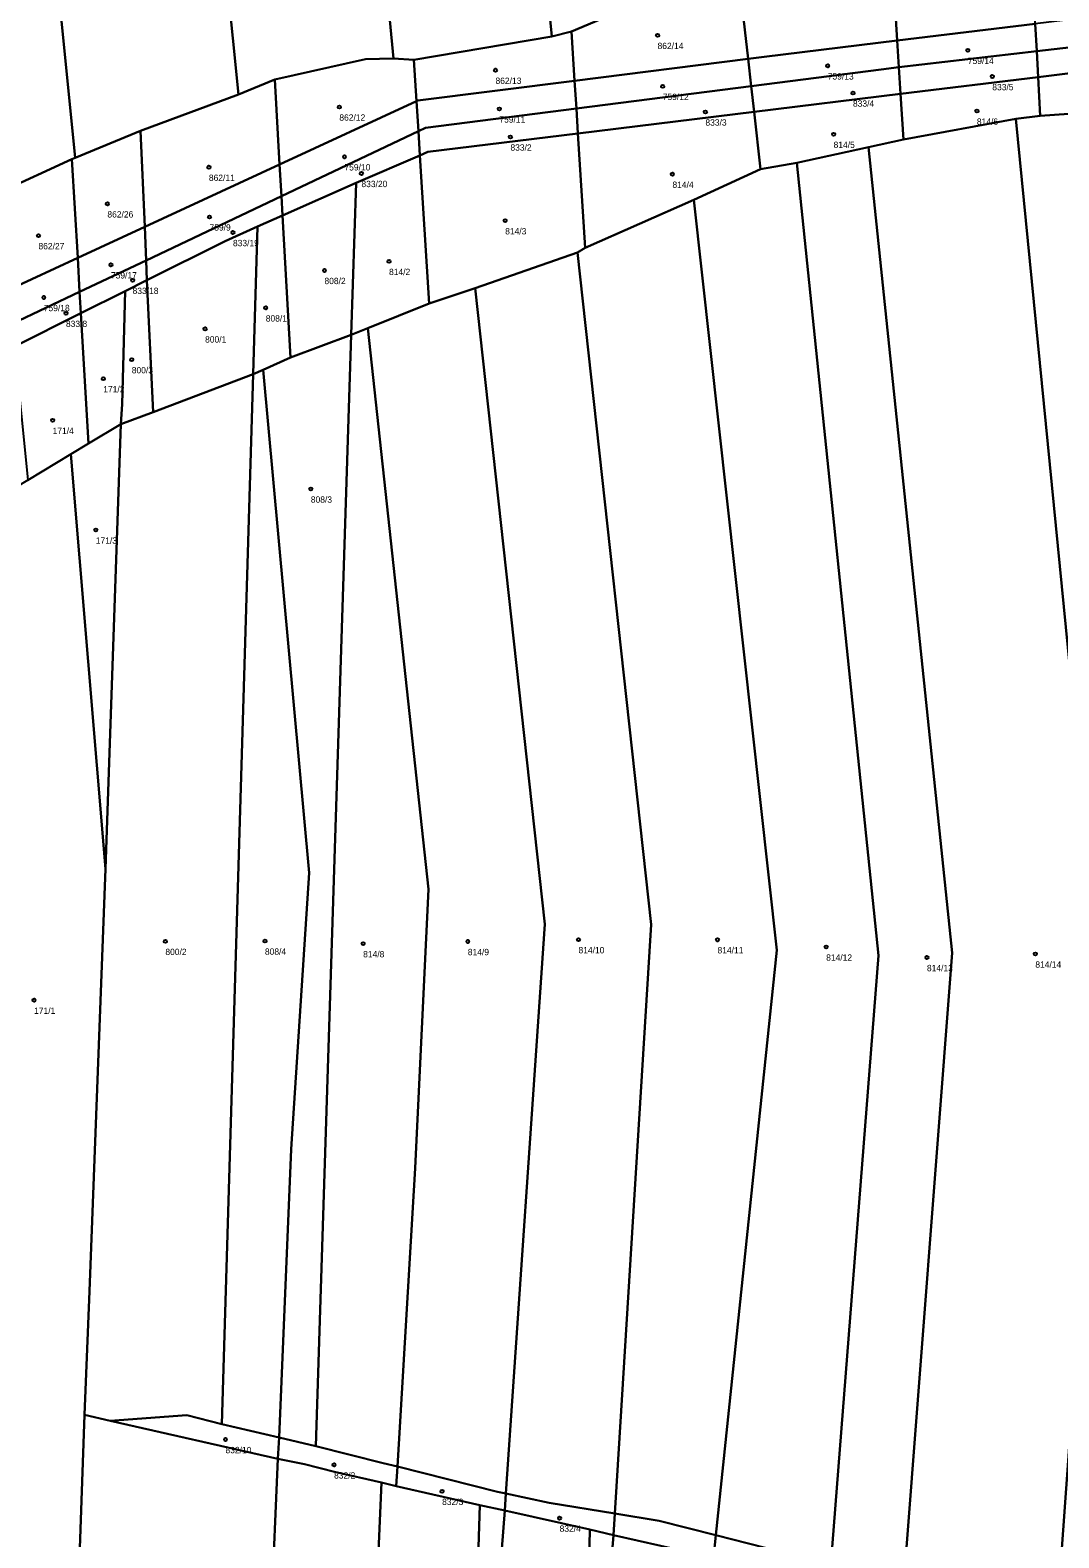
# Model space of a CAD drawing. Extents: x -587171 to -555306, y -1167727 to -1074732.
# Drawn here: x -585632 to -585469.6, y -1165047.9 to -1164809.8 of the extents above; entities that cross this region are included whole.
import ezdxf

# ---------------------------------------------------------------- set-up
doc = ezdxf.new("R2010")
doc.units = 0
doc.layers.add('Definiční body', color=7, linetype='Continuous')
doc.layers.add('Polygon parcely', color=7, linetype='Continuous')

msp = doc.modelspace()

# ---------------------------------------------------------------- linework, layer by layer
at = {"layer": 'Definiční body'}
for centre in [(-585532.92, -1164810.65), (-585483.92, -1164813.01), (-585558.51, -1164816.15), (-585506.04, -1164815.46), (-585480.06, -1164817.15), (-585532.1, -1164818.7), (-585583.17, -1164821.96), (-585502.06, -1164819.75), (-585557.9, -1164822.27), (-585525.36, -1164822.74), (-585482.49, -1164822.6), (-585556.15, -1164826.69), (-585505.12, -1164826.27), (-585603.77, -1164831.47), (-585582.36, -1164829.82), (-585579.68, -1164832.45), (-585530.57, -1164832.57), (-585619.8, -1164837.25), (-585603.67, -1164839.32), (-585556.98, -1164839.92), (-585630.68, -1164842.27), (-585599.97, -1164841.78), (-585619.24, -1164846.88), (-585585.52, -1164847.77), (-585575.32, -1164846.34), (-585615.82, -1164849.33), (-585629.84, -1164852.04), (-585626.34, -1164854.54), (-585594.79, -1164853.68), (-585604.37, -1164857), (-585615.95, -1164861.86), (-585620.45, -1164864.87), (-585628.45, -1164871.43), (-585587.67, -1164882.29), (-585621.63, -1164888.77), (-585610.64, -1164953.73), (-585594.92, -1164953.68), (-585579.41, -1164954.09), (-585562.88, -1164953.75), (-585545.4, -1164953.45), (-585523.45, -1164953.47), (-585506.29, -1164954.62), (-585490.38, -1164956.28), (-585473.26, -1164955.72), (-585631.37, -1164963.01), (-585601.15, -1165032.4), (-585584, -1165036.4), (-585566.94, -1165040.58), (-585548.39, -1165044.81)]:
    msp.add_circle(centre, 0.25, dxfattribs=at)
at = {"layer": 'Polygon parcely'}
for points in [[(-585551, -1164580.28), (-585573.84, -1164584.79), (-585561.86, -1164685.88), (-585549.62, -1164810.82), (-585546.52, -1164810.02), (-585526.98, -1164801.79), (-585538.96, -1164683.24)], [(-585573.84, -1164584.79), (-585598.1, -1164589.57), (-585585.8, -1164697.59), (-585574.62, -1164814.28), (-585571.39, -1164814.49), (-585549.62, -1164810.82), (-585561.86, -1164685.88)], [(-585610.53, -1164706.4), (-585599.09, -1164819.98), (-585593.35, -1164817.59), (-585579.04, -1164814.41), (-585574.62, -1164814.28), (-585585.8, -1164697.59), (-585598.1, -1164589.57), (-585611.87, -1164592.28), (-585621.99, -1164594.46)], [(-585647.86, -1164600.03), (-585636.36, -1164715.01), (-585624.87, -1164829.97), (-585614.56, -1164825.73), (-585599.09, -1164819.98), (-585610.53, -1164706.4), (-585621.99, -1164594.46)], [(-585624.87, -1164829.97), (-585636.36, -1164715.01), (-585647.86, -1164600.03), (-585673.24, -1164605.5), (-585661.76, -1164722.49), (-585650.38, -1164838.45), (-585636.88, -1164835.45), (-585625.4, -1164830.19)], [(-585475.09, -1164775.69), (-585476.81, -1164776.66), (-585494.84, -1164785.46), (-585496.61, -1164786.37), (-585495.06, -1164811.47), (-585473.28, -1164808.8)], [(-585495.06, -1164811.47), (-585496.61, -1164786.37), (-585503.91, -1164790.2), (-585520.33, -1164799.18), (-585518.61, -1164814.37), (-585516.08, -1164814.05)], [(-585520.33, -1164799.18), (-585526.98, -1164801.79), (-585546.52, -1164810.02), (-585546.02, -1164817.81), (-585518.61, -1164814.37)], [(-585473.04, -1164813.15), (-585454.28, -1164810.97), (-585454.82, -1164806.58), (-585458.23, -1164806.96), (-585473.28, -1164808.8)], [(-585473.28, -1164808.8), (-585495.06, -1164811.47), (-585494.8, -1164815.68), (-585473.04, -1164813.15)], [(-585546.52, -1164810.02), (-585549.62, -1164810.82), (-585571.39, -1164814.49), (-585570.99, -1164821.02), (-585570.78, -1164820.92), (-585546.02, -1164817.81)], [(-585516.08, -1164814.05), (-585518.61, -1164814.37), (-585518.13, -1164818.65), (-585497.6, -1164816.01), (-585494.8, -1164815.68), (-585495.06, -1164811.47)], [(-585454.28, -1164810.97), (-585473.04, -1164813.15), (-585472.82, -1164817.23), (-585453.8, -1164814.9)], [(-585571.39, -1164814.49), (-585574.62, -1164814.28), (-585579.04, -1164814.41), (-585593.35, -1164817.59), (-585592.6, -1164831.03), (-585570.99, -1164821.02)], [(-585518.61, -1164814.37), (-585546.02, -1164817.81), (-585545.74, -1164822.19), (-585518.13, -1164818.65)], [(-585473.04, -1164813.15), (-585494.8, -1164815.68), (-585494.54, -1164819.9), (-585472.82, -1164817.23)], [(-585494.54, -1164819.9), (-585494.8, -1164815.68), (-585497.6, -1164816.01), (-585518.13, -1164818.65), (-585517.67, -1164822.74)], [(-585453.8, -1164814.9), (-585472.82, -1164817.23), (-585472.49, -1164823.33), (-585452.91, -1164821.98)], [(-585599.09, -1164819.98), (-585614.56, -1164825.73), (-585613.91, -1164840.9), (-585592.6, -1164831.03), (-585593.35, -1164817.59)], [(-585569.55, -1164825.25), (-585545.74, -1164822.19), (-585546.02, -1164817.81), (-585570.78, -1164820.92), (-585570.99, -1164821.02), (-585570.69, -1164825.79)], [(-585518.13, -1164818.65), (-585545.74, -1164822.19), (-585545.49, -1164826.15), (-585517.67, -1164822.74)], [(-585472.82, -1164817.23), (-585494.54, -1164819.9), (-585494.1, -1164827.1), (-585476.36, -1164823.84), (-585472.49, -1164823.33)], [(-585592.32, -1164836.05), (-585570.69, -1164825.79), (-585570.99, -1164821.02), (-585592.6, -1164831.03)], [(-585494.54, -1164819.9), (-585517.67, -1164822.74), (-585516.64, -1164831.79), (-585510.93, -1164830.77), (-585499.61, -1164828.32), (-585494.1, -1164827.1)], [(-585570.69, -1164825.79), (-585570.46, -1164829.6), (-585569.21, -1164829.06), (-585545.49, -1164826.15), (-585545.74, -1164822.19), (-585569.55, -1164825.25)], [(-585517.67, -1164822.74), (-585545.49, -1164826.15), (-585544.34, -1164844.22), (-585527.17, -1164836.6), (-585516.64, -1164831.79)], [(-585494.02, -1165054.9), (-585469.81, -1165059.87), (-585462.77, -1164961.88), (-585476.36, -1164823.84), (-585494.1, -1164827.1), (-585499.61, -1164828.32), (-585486.42, -1164955.51)], [(-585469.81, -1165059.87), (-585453.22, -1165063.28), (-585446.33, -1165065.05), (-585438.3, -1164967.29), (-585452.91, -1164821.98), (-585472.49, -1164823.33), (-585476.36, -1164823.84), (-585462.77, -1164961.88)], [(-585614.56, -1164825.73), (-585624.87, -1164829.97), (-585625.4, -1164830.19), (-585624.49, -1164845.8), (-585613.91, -1164840.9)], [(-585570.69, -1164825.79), (-585592.32, -1164836.05), (-585592.15, -1164839.09), (-585580.53, -1164833.93), (-585570.46, -1164829.6)], [(-585569.01, -1164852.99), (-585561.71, -1164850.58), (-585545.56, -1164844.94), (-585544.34, -1164844.22), (-585545.49, -1164826.15), (-585569.21, -1164829.06), (-585570.46, -1164829.6)], [(-585486.42, -1164955.51), (-585499.61, -1164828.32), (-585510.93, -1164830.77), (-585498.01, -1164955.95), (-585505.57, -1165052.12), (-585497.3, -1165054.23), (-585494.02, -1165054.9)], [(-585635.35, -1164850.83), (-585624.49, -1164845.8), (-585625.4, -1164830.19), (-585636.88, -1164835.45)], [(-585592.32, -1164836.05), (-585592.6, -1164831.03), (-585613.91, -1164840.9), (-585613.68, -1164846.19)], [(-585570.46, -1164829.6), (-585580.53, -1164833.93), (-585581.3, -1164857.96), (-585578.66, -1164856.89), (-585569.01, -1164852.99)], [(-585498.01, -1164955.95), (-585510.93, -1164830.77), (-585516.64, -1164831.79), (-585527.17, -1164836.6), (-585514.08, -1164955.09), (-585523.71, -1165047.5), (-585505.57, -1165052.12)], [(-585580.53, -1164833.93), (-585592.15, -1164839.09), (-585590.89, -1164861.52), (-585581.3, -1164857.96)], [(-585592.15, -1164839.09), (-585592.32, -1164836.05), (-585613.68, -1164846.19), (-585613.55, -1164849.3), (-585601.21, -1164843.17), (-585596.1, -1164840.84)], [(-585523.71, -1165047.5), (-585514.08, -1164955.09), (-585527.17, -1164836.6), (-585544.34, -1164844.22), (-585545.56, -1164844.94), (-585533.95, -1164951.05), (-585539.64, -1165044.09), (-585532.66, -1165045.22)], [(-585592.15, -1164839.09), (-585596.1, -1164840.84), (-585596.8, -1164864.16), (-585595.18, -1164863.46), (-585590.89, -1164861.52)], [(-585613.91, -1164840.9), (-585624.49, -1164845.8), (-585624.18, -1164851.17), (-585613.68, -1164846.19)], [(-585613.55, -1164849.3), (-585612.59, -1164870.14), (-585596.8, -1164864.16), (-585596.1, -1164840.84), (-585601.21, -1164843.17)], [(-585533.95, -1164951.05), (-585545.56, -1164844.94), (-585561.71, -1164850.58), (-585550.72, -1164951.02), (-585556.88, -1165040.94), (-585550.04, -1165042.4), (-585539.64, -1165044.09)], [(-585634.82, -1164856.22), (-585624.18, -1164851.17), (-585624.49, -1164845.8), (-585635.35, -1164850.83)], [(-585613.68, -1164846.19), (-585624.18, -1164851.17), (-585623.98, -1164854.52), (-585617, -1164851.02), (-585613.55, -1164849.3)], [(-585613.55, -1164849.3), (-585617, -1164851.02), (-585617.47, -1164868.89), (-585617.68, -1164872.02), (-585612.59, -1164870.14)], [(-585634.47, -1164859.77), (-585623.98, -1164854.52), (-585624.18, -1164851.17), (-585634.82, -1164856.22)], [(-585622.78, -1164875.09), (-585617.68, -1164872.02), (-585617.47, -1164868.89), (-585617, -1164851.02), (-585623.98, -1164854.52)], [(-585550.72, -1164951.02), (-585561.71, -1164850.58), (-585569.01, -1164852.99), (-585578.66, -1164856.89), (-585569.08, -1164945.47), (-585571.21, -1164989.55), (-585574.01, -1165036.68), (-585558.18, -1165040.66), (-585556.88, -1165040.94)], [(-585632.37, -1164880.88), (-585625.56, -1164876.77), (-585622.78, -1164875.09), (-585623.98, -1164854.52), (-585634.47, -1164859.77)], [(-585586.89, -1165033.43), (-585576.26, -1165036.11), (-585574.01, -1165036.68), (-585571.21, -1164989.55), (-585569.08, -1164945.47), (-585578.66, -1164856.89), (-585581.3, -1164857.96)], [(-585586.89, -1165033.43), (-585581.3, -1164857.96), (-585590.89, -1164861.52), (-585595.18, -1164863.46), (-585587.96, -1164942.88), (-585590.8, -1164986.54), (-585592.65, -1165032.09)], [(-585619.37, -1165029.43), (-585607.26, -1165028.55), (-585601.75, -1165029.96), (-585596.8, -1164864.16), (-585612.59, -1164870.14), (-585617.68, -1164872.02), (-585620.11, -1164942.28), (-585622.62, -1165008.99), (-585623.4, -1165028.51)], [(-585601.75, -1165029.96), (-585592.65, -1165032.09), (-585590.8, -1164986.54), (-585587.96, -1164942.88), (-585595.18, -1164863.46), (-585596.8, -1164864.16)], [(-585617.68, -1164872.02), (-585622.78, -1164875.09), (-585625.56, -1164876.77), (-585620.11, -1164942.28)], [(-585620.11, -1164942.28), (-585625.56, -1164876.77), (-585632.37, -1164880.88), (-585639.6, -1164885.25), (-585641.63, -1164944.06), (-585644.54, -1165009.52), (-585647.29, -1165080.2), (-585634.12, -1165081.32), (-585633.19, -1165071.69), (-585630.15, -1165071.93), (-585629.82, -1165067.18), (-585624.78, -1165067.6), (-585623.4, -1165028.51), (-585622.62, -1165008.99)], [(-585592.88, -1165035.44), (-585619.37, -1165029.43), (-585623.4, -1165028.51), (-585624.78, -1165067.6), (-585625.44, -1165082.08), (-585625.97, -1165104.41), (-585618.63, -1165104.92), (-585619.06, -1165111.52), (-585626.13, -1165111.08), (-585626.22, -1165114.94), (-585626.31, -1165118.74), (-585627.22, -1165124.11), (-585627.48, -1165125.63), (-585596.86, -1165129.34)], [(-585619.37, -1165029.43), (-585592.88, -1165035.44), (-585592.65, -1165032.09), (-585601.75, -1165029.96), (-585607.26, -1165028.55)], [(-585576.52, -1165039.2), (-585574.19, -1165039.74), (-585574.01, -1165036.68), (-585576.26, -1165036.11), (-585586.89, -1165033.43), (-585592.65, -1165032.09), (-585592.88, -1165035.44), (-585588.65, -1165036.28), (-585583.92, -1165037.49)], [(-585580.27, -1165126.1), (-585580.07, -1165121.48), (-585593.03, -1165120.8), (-585592.6, -1165110.67), (-585584.23, -1165111.19), (-585584.17, -1165110.28), (-585579.61, -1165110.53), (-585576.52, -1165039.2), (-585583.92, -1165037.49), (-585588.65, -1165036.28), (-585592.88, -1165035.44), (-585596.86, -1165129.34), (-585584.17, -1165131.21), (-585580.52, -1165131.87), (-585580.48, -1165130.87)], [(-585557.06, -1165043.58), (-585556.88, -1165040.94), (-585558.18, -1165040.66), (-585574.01, -1165036.68), (-585574.19, -1165039.74), (-585561, -1165042.78)], [(-585579.61, -1165110.53), (-585579.67, -1165112.03), (-585571.08, -1165112.37), (-585571.16, -1165115.01), (-585567.59, -1165115.14), (-585567.94, -1165122.84), (-585571.81, -1165122.7), (-585571.75, -1165121.81), (-585580.07, -1165121.48), (-585580.27, -1165126.1), (-585577.88, -1165126.27), (-585578.23, -1165131.04), (-585580.48, -1165130.87), (-585580.52, -1165131.87), (-585564.1, -1165134.8), (-585561.8, -1165067.61), (-585561, -1165042.78), (-585574.19, -1165039.74), (-585576.52, -1165039.2)], [(-585559.23, -1165071.87), (-585557.06, -1165043.58), (-585561, -1165042.78), (-585561.8, -1165067.61), (-585564.1, -1165134.8)], [(-585539.64, -1165044.09), (-585550.04, -1165042.4), (-585556.88, -1165040.94), (-585557.06, -1165043.58), (-585543.62, -1165046.63), (-585539.87, -1165047.48)], [(-585543.62, -1165046.63), (-585557.06, -1165043.58), (-585559.23, -1165071.87), (-585544.21, -1165073.37)], [(-585524.06, -1165051.08), (-585523.71, -1165047.5), (-585532.66, -1165045.22), (-585539.64, -1165044.09), (-585539.87, -1165047.48), (-585528.66, -1165050.03)], [(-585530.29, -1165118.25), (-585530.15, -1165112.19), (-585530.6, -1165112.16), (-585533.28, -1165111.95), (-585532.86, -1165107.03), (-585532.58, -1165104.06), (-585530.35, -1165104.21), (-585528.66, -1165050.03), (-585539.87, -1165047.48), (-585542.04, -1165073.59), (-585545.52, -1165114.65), (-585545.69, -1165116.64)], [(-585539.87, -1165047.48), (-585543.62, -1165046.63), (-585544.21, -1165073.37), (-585542.04, -1165073.59)], [(-585505.84, -1165055.05), (-585505.57, -1165052.12), (-585523.71, -1165047.5), (-585524.06, -1165051.08), (-585518.56, -1165052.19), (-585513.89, -1165053.25)]]:
    msp.add_lwpolyline(points, close=True, dxfattribs=at)

# ---------------------------------------------------------------- texts
at = {"layer": 'Definiční body'}
for s, p in [('862/14', (-585532.92, -1164812.81)), ('759/14', (-585483.92, -1164815.17)), ('759/13', (-585506.04, -1164817.62)), ('862/13', (-585558.51, -1164818.31)), ('833/5', (-585480.06, -1164819.31)), ('759/12', (-585532.1, -1164820.86)), ('833/4', (-585502.06, -1164821.91)), ('862/12', (-585583.17, -1164824.12)), ('759/11', (-585557.9, -1164824.43)), ('833/3', (-585525.36, -1164824.9)), ('814/6', (-585482.49, -1164824.76)), ('833/2', (-585556.15, -1164828.85)), ('814/5', (-585505.12, -1164828.43)), ('759/10', (-585582.36, -1164831.98)), ('862/11', (-585603.77, -1164833.63)), ('833/20', (-585579.68, -1164834.61)), ('814/4', (-585530.57, -1164834.73)), ('862/26', (-585619.8, -1164839.41)), ('759/9', (-585603.67, -1164841.48)), ('833/19', (-585599.97, -1164843.94)), ('814/3', (-585556.98, -1164842.08)), ('862/27', (-585630.68, -1164844.43)), ('814/2', (-585575.32, -1164848.5)), ('759/17', (-585619.24, -1164849.04)), ('808/2', (-585585.52, -1164849.93)), ('833/18', (-585615.82, -1164851.49)), ('759/18', (-585629.84, -1164854.2)), ('808/1', (-585594.79, -1164855.84)), ('833/8', (-585626.34, -1164856.7)), ('800/1', (-585604.37, -1164859.16)), ('800/3', (-585615.95, -1164864.02)), ('171/2', (-585620.45, -1164867.03)), ('171/4', (-585628.45, -1164873.59)), ('808/3', (-585587.67, -1164884.45)), ('171/3', (-585621.63, -1164890.93)), ('800/2', (-585610.64, -1164955.89)), ('808/4', (-585594.92, -1164955.84)), ('814/9', (-585562.88, -1164955.91)), ('814/10', (-585545.4, -1164955.61)), ('814/11', (-585523.45, -1164955.63)), ('814/8', (-585579.41, -1164956.25)), ('814/12', (-585506.29, -1164956.78)), ('814/13', (-585490.38, -1164958.44)), ('814/14', (-585473.26, -1164957.88)), ('171/1', (-585631.37, -1164965.17)), ('832/10', (-585601.15, -1165034.56)), ('832/2', (-585584, -1165038.56)), ('832/3', (-585566.94, -1165042.74)), ('832/4', (-585548.39, -1165046.97))]:
    msp.add_text(s, height=1, dxfattribs=at).set_placement(p)

doc.saveas('drawing.dxf')
